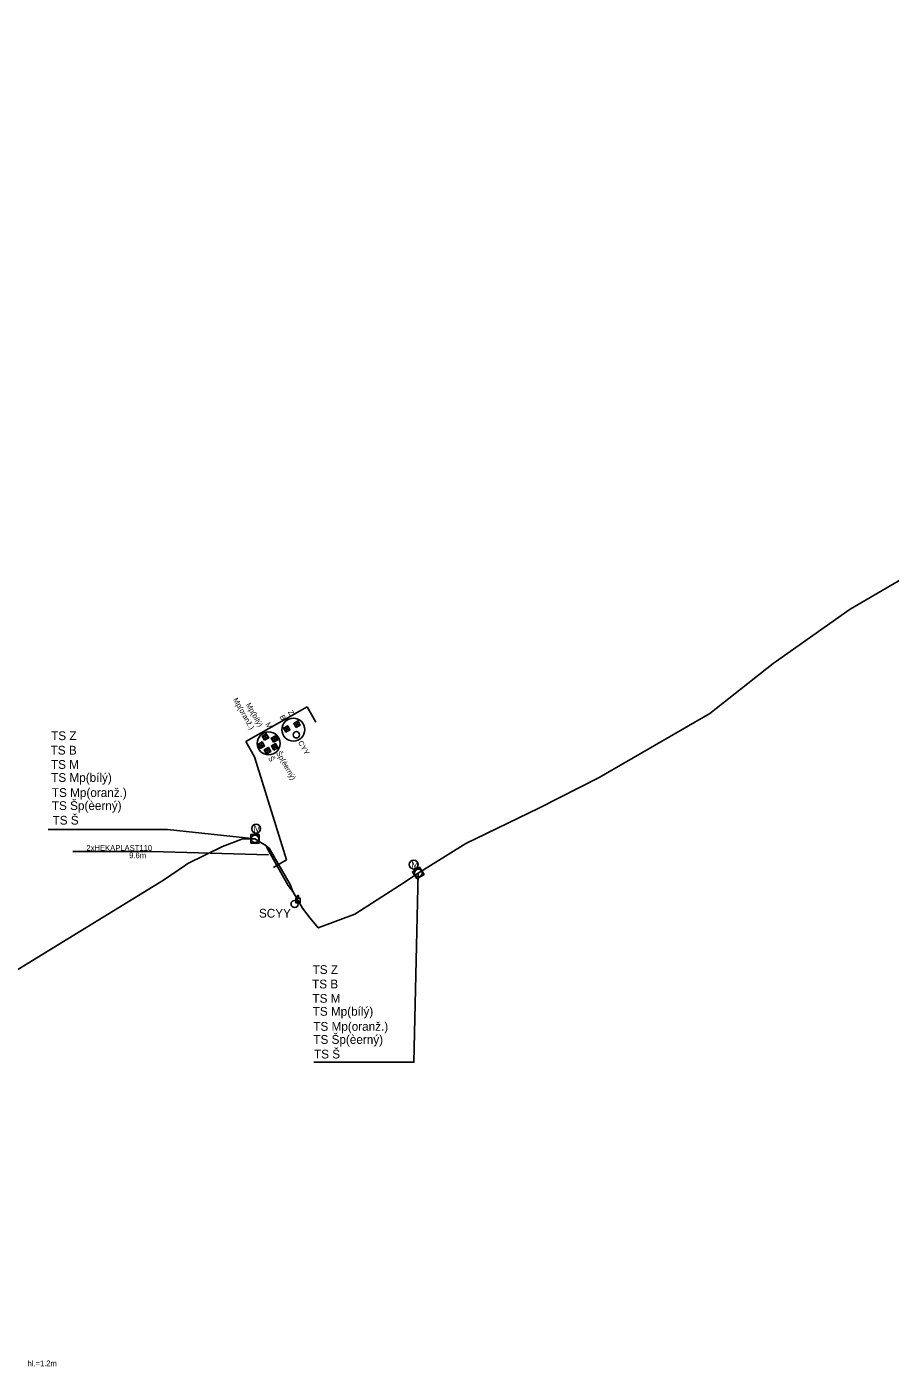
# Model space of a CAD drawing. Extents: x -566419 to -564928, y -1204142 to -1203285.
# Drawn here: x -565716 to -565519, y -1203663.9 to -1203358.1 of the extents above; entities that cross this region are included whole.
import ezdxf

# ---------------------------------------------------------------- set-up
doc = ezdxf.new("R2010")
doc.units = 0
for name, color, linetype in [('Trasa DialT', 7, 'Continuous'), ('Vrstva 10', 7, 'Continuous'), ('Vrstva 13', 7, 'Continuous'), ('Vrstva 14', 7, 'Continuous'), ('Vrstva 4', 7, 'Continuous'), ('Vrstva 58', 7, 'Continuous'), ('Vrstva 59', 7, 'Continuous'), ('Vrstva 61', 7, 'Continuous')]:
    doc.layers.add(name, color=color, linetype=linetype)

msp = doc.modelspace()

# ---------------------------------------------------------------- linework, layer by layer
at = {"layer": 'Trasa DialT'}
for points in [[(-565653.11, -1203559.27), (-565651.39, -1203561.56), (-565649.55, -1203563.81), (-565641.19, -1203560.67), (-565631.01, -1203554.09), (-565626.71, -1203551.28), (-565615.87, -1203544.51), (-565599.22, -1203536.47), (-565585.44, -1203529.47), (-565560.21, -1203514.82), (-565545.75, -1203503.47), (-565528.16, -1203491.01), (-565502.58, -1203476.14), (-565482.73, -1203465.01), (-565459.85, -1203451.03), (-565422.54, -1203429.16), (-565376.31, -1203401.4), (-565341.42, -1203381.36), (-565302.79, -1203358.08)], [(-565718.08, -1203573.28), (-565684.87, -1203552.9), (-565679.8, -1203549.46), (-565679.27, -1203549.1), (-565671.4, -1203545.21), (-565666.97, -1203543.53), (-565663.98, -1203543.46), (-565661.46, -1203544.99), (-565660.72, -1203545.62), (-565655.92, -1203553.89), (-565655.3, -1203555.48), (-565653.11, -1203559.27)], [(-565661.46, -1203544.99), (-565661.08, -1203545.71), (-565656.4, -1203554.09), (-565655.3, -1203555.48)]]:
    msp.add_lwpolyline(points, dxfattribs=at)
at = {"layer": 'Vrstva 10'}
for p, q in [((-565652.07, -1203513.33), (-565666.07, -1203521.28)), ((-565650.09, -1203516.81), (-565652.07, -1203513.33)), ((-565656.92, -1203519.14), (-565656.51, -1203517.66)), ((-565655.12, -1203517.1), (-565653.64, -1203517.51)), ((-565654.58, -1203518.05), (-565654.17, -1203516.56)), ((-565662.33, -1203520), (-565660.84, -1203520.41)), ((-565661.79, -1203520.95), (-565661.38, -1203519.47)), ((-565660.27, -1203520.47), (-565658.79, -1203520.88)), ((-565659.74, -1203521.42), (-565659.32, -1203519.93)), ((-565657.46, -1203518.19), (-565655.98, -1203518.6)), ((-565666.07, -1203521.28), (-565664.1, -1203524.76)), ((-565663.3, -1203521.89), (-565661.82, -1203522.3)), ((-565662.77, -1203522.84), (-565662.35, -1203521.35)), ((-565661.84, -1203523.15), (-565660.36, -1203523.56)), ((-565661.31, -1203524.1), (-565660.89, -1203522.61)), ((-565660.21, -1203522.24), (-565658.72, -1203522.65)), ((-565659.67, -1203523.19), (-565659.26, -1203521.71)), ((-565664.1, -1203524.76), (-565656.8, -1203548.25)), ((-565656.8, -1203548.25), (-565659.75, -1203550.04))]:
    msp.add_line(p, q, dxfattribs=at)
for points in [[(-565656.92, -1203519.14), (-565655.98, -1203518.6), (-565656.51, -1203517.66), (-565657.46, -1203518.19)], [(-565654.58, -1203518.05), (-565653.64, -1203517.51), (-565654.17, -1203516.56), (-565655.12, -1203517.1)], [(-565661.79, -1203520.95), (-565660.84, -1203520.41), (-565661.38, -1203519.47), (-565662.33, -1203520)], [(-565659.74, -1203521.42), (-565658.79, -1203520.88), (-565659.32, -1203519.93), (-565660.27, -1203520.47)], [(-565662.77, -1203522.84), (-565661.82, -1203522.3), (-565662.35, -1203521.35), (-565663.3, -1203521.89)], [(-565661.31, -1203524.1), (-565660.36, -1203523.56), (-565660.89, -1203522.61), (-565661.84, -1203523.15)], [(-565659.67, -1203523.19), (-565658.72, -1203522.65), (-565659.26, -1203521.71), (-565660.21, -1203522.24)]]:
    msp.add_lwpolyline(points, close=True, dxfattribs=at)
for centre, radius in [((-565655.21, -1203518.54), 2.6), ((-565660.84, -1203521.67), 2.6), ((-565654.52, -1203519.71), 0.726)]:
    msp.add_circle(centre, radius, dxfattribs=at)
at = {"layer": 'Vrstva 13'}
for points in [[(-565661.08, -1203545.71), (-565656.4, -1203554.09)], [(-565660.72, -1203545.62), (-565655.92, -1203553.89)]]:
    msp.add_lwpolyline(points, dxfattribs=at)
at = {"layer": 'Vrstva 14'}
for points in [[(-565663.98, -1203543.46), (-565683.94, -1203541.36), (-565711.14, -1203541.36)], [(-565626.71, -1203551.28), (-565627.71, -1203594.45), (-565650.55, -1203594.45)]]:
    msp.add_lwpolyline(points, dxfattribs=at)
for points in [[(-565664.94, -1203544.42), (-565663.02, -1203544.42), (-565663.02, -1203542.5), (-565664.94, -1203542.5)], [(-565627.02, -1203552.6), (-565625.39, -1203551.59), (-565626.4, -1203549.96), (-565628.03, -1203550.97)]]:
    msp.add_lwpolyline(points, close=True, dxfattribs=at)
for centre in [(-565663.98, -1203543.46), (-565626.71, -1203551.28)]:
    msp.add_circle(centre, 0.864, dxfattribs=at)
at = {"layer": 'Vrstva 4'}
msp.add_lwpolyline([(-565654.66, -1203557.03), (-565653.65, -1203557.03), (-565653.65, -1203558.04), (-565654.66, -1203558.04)], close=True, dxfattribs=at)
msp.add_lwpolyline([(-565654.03, -1203557.03), (-565654.03, -1203556.4), (-565654.28, -1203556.4), (-565654.28, -1203557.03)], dxfattribs=at)
at = {"layer": 'Vrstva 59'}
for centre, radius in [((-565663.72, -1203541.14), 1), ((-565627.77, -1203549.35), 1), ((-565654.92, -1203558.34), 0.825)]:
    msp.add_circle(centre, radius, dxfattribs=at)
at = {"layer": 'Vrstva 61'}
for p, q in [((-565687.48, -1203546.39), (-565705.53, -1203546.39)), ((-565660.86, -1203547.13), (-565687.48, -1203546.39))]:
    msp.add_line(p, q, dxfattribs=at)

# ---------------------------------------------------------------- texts
at = {"layer": 'Vrstva 10'}
for s, p in [('Mp(oranž.)', (-565669.01, -1203511.68)), ('Mp(bílý)', (-565666.08, -1203512.83)), ('Z', (-565656.51, -1203514.51)), ('M', (-565661.63, -1203517.28)), ('B', (-565658.4, -1203515.58)), ('Šp(èerný)', (-565659.19, -1203523.85)), ('CYY', (-565654.2, -1203521.46)), ('Š', (-565661, -1203525.02))]:
    msp.add_text(s, height=1.2, rotation=299.5161, dxfattribs=at).set_placement(p)
at = {"layer": 'Vrstva 14'}
for s, p in [('TS Z', (-565710.48, -1203520.93)), ('TS B', (-565710.59, -1203524.23)), ('TS M', (-565710.52, -1203527.49)), ('TS Mp(bílý)', (-565710.46, -1203530.47)), ('TS Mp(oranž.)', (-565710.31, -1203533.9)), ('TS Šp(èerný)', (-565710.31, -1203536.88)), ('TS Š', (-565710.15, -1203540.22)), ('TS Z', (-565650.82, -1203574.31)), ('TS B', (-565650.94, -1203577.61)), ('TS M', (-565650.86, -1203580.88)), ('TS Mp(bílý)', (-565650.8, -1203583.85)), ('TS Mp(oranž.)', (-565650.66, -1203587.28)), ('TS Šp(èerný)', (-565650.65, -1203590.27)), ('TS Š', (-565650.5, -1203593.6))]:
    msp.add_text(s, height=2, dxfattribs=at).set_placement(p)
at = {"layer": 'Vrstva 58'}
msp.add_text('SCYY', height=2, dxfattribs=at).set_placement((-565663.06, -1203561.45))
at = {"layer": 'Vrstva 59'}
for p in [(-565664.28, -1203541.89), (-565628.33, -1203550.09)]:
    msp.add_text('M', height=1.5, dxfattribs=at).set_placement(p)
at = {"layer": 'Vrstva 61'}
for s, p in [('2xHEKAPLAST110', (-565702.43, -1203546.19)), ('9.6m', (-565692.68, -1203547.89)), ('hl.=1.2m', (-565715.88, -1203663.86))]:
    msp.add_text(s, height=1.3, dxfattribs=at).set_placement(p)

doc.saveas('drawing.dxf')
